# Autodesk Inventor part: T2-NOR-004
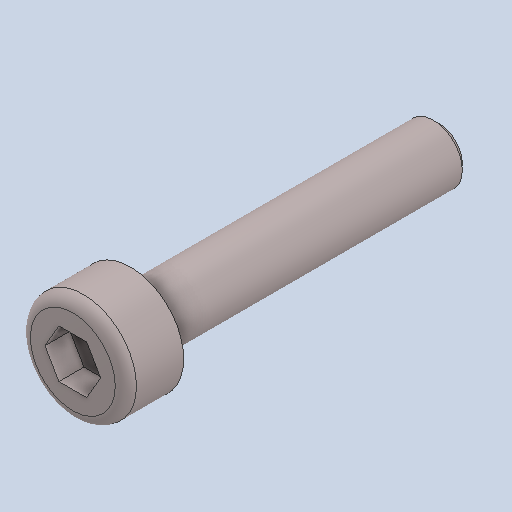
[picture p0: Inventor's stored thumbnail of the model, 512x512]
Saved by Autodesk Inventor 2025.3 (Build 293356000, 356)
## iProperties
Created: 2020-02
Part Number: T2-NOR-004
Material: Genérico
Description: Tornillo de cabeza cilíndrica con hexágono interior M3 × 16 mm
Document SubType Name: Modeling
Designer: Luis MuÃ±oz
Authority: Unknown
Density: 1 g/cm^3
Appearance: Valor por defecto
Project: TESIS 2 - Plataforma mecatrÃ³nica preventiva desacoplada
Sending System: FreeCAD
Preprocessor: Open CASCADE STEP processor 7.3
Title: Tornillo de cabeza cilÃ­ndrica con hexÃ¡gono interior M3 Ã— 16 mm
Author: Author
Revision Number: 00
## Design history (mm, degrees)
feature "Base1"
node "Sólido1"
